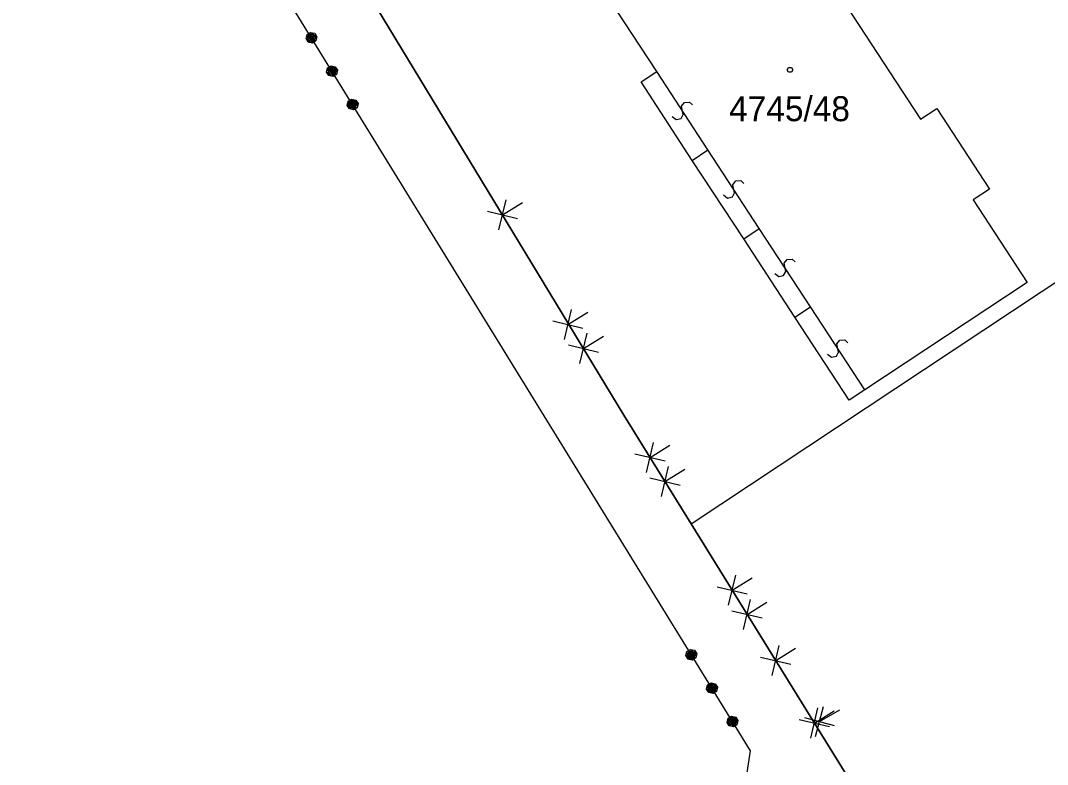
# Model space of a CAD drawing. Extents: x -266179 to -264727, y -1243225 to -1241702.
# Drawn here: x -265771.7 to -265705.9, y -1242086.5 to -1242038.9 of the extents above; entities that cross this region are included whole.
import ezdxf

# ---------------------------------------------------------------- set-up
doc = ezdxf.new("R2010")
doc.units = 0
for name, color, linetype in [('Vrstva 1', 7, 'Continuous'), ('Vrstva 19', 7, 'Continuous'), ('Vrstva 2', 7, 'Continuous'), ('Vrstva 21', 7, 'Continuous')]:
    doc.layers.add(name, color=color, linetype=linetype)

msp = doc.modelspace()

# ---------------------------------------------------------------- linework, layer by layer
at = {"layer": 'Vrstva 1'}
for p, q in [((-265771.66, -1242000.45), (-265733.03, -1242064.16)), ((-265720.51, -1242035.32), (-265714.05, -1242045.2)), ((-265730.93, -1242042.16), (-265734.17, -1242037.2)), ((-265724.93, -1242085.65), (-265754.18, -1242038.14)), ((-265731.93, -1242042.82), (-265730.93, -1242042.16)), ((-265728.65, -1242047.85), (-265731.93, -1242042.82)), ((-265714.05, -1242045.2), (-265713, -1242044.52)), ((-265713, -1242044.52), (-265709.62, -1242049.7)), ((-265725.36, -1242052.87), (-265728.65, -1242047.85)), ((-265709.62, -1242049.7), (-265710.67, -1242050.38)), ((-265710.67, -1242050.38), (-265707.22, -1242055.66)), ((-265722.08, -1242057.89), (-265725.36, -1242052.87)), ((-265728.73, -1242071.12), (-265701.71, -1242053.21)), ((-265707.22, -1242055.66), (-265717.61, -1242062.55)), ((-265718.61, -1242063.21), (-265722.08, -1242057.89)), ((-265717.61, -1242062.55), (-265718.61, -1242063.21)), ((-265733.03, -1242064.16), (-265728.73, -1242071.12)), ((-265728.73, -1242071.12), (-265715.42, -1242092.63)), ((-265733.05, -1242138.92), (-265724.93, -1242085.65))]:
    msp.add_line(p, q, dxfattribs=at)
msp.add_lwpolyline([(-265722.31, -1242041.9), (-265722.22, -1242042.05), (-265722.31, -1242042.2), (-265722.49, -1242042.2), (-265722.58, -1242042.05), (-265722.49, -1242041.9)], close=True, dxfattribs=at)
at = {"layer": 'Vrstva 19'}
for p, q in [((-265724.93, -1242085.65), (-265754.18, -1242038.14)), ((-265733.05, -1242138.92), (-265724.93, -1242085.65))]:
    msp.add_line(p, q, dxfattribs=at)
for points in [[(-265753.378, -1242040.054), (-265753.316, -1242039.793), (-265753.087, -1242039.651), (-265752.825, -1242039.713), (-265752.683, -1242039.943), (-265752.746, -1242040.204), (-265752.975, -1242040.346), (-265753.237, -1242040.284), (-265753.378, -1242040.054), (-265753.323, -1242040.067), (-265753.198, -1242040.271), (-265753.098, -1242040.281), (-265753.297, -1242039.957), (-265753.271, -1242039.847), (-265752.998, -1242040.29), (-265752.93, -1242040.248), (-265753.203, -1242039.805), (-265753.135, -1242039.763), (-265752.862, -1242040.206), (-265752.789, -1242040.172), (-265753.062, -1242039.73), (-265752.972, -1242039.722), (-265752.757, -1242040.071), (-265752.716, -1242039.986), (-265752.841, -1242039.782)], [(-265752.062, -1242042.191), (-265752, -1242041.93), (-265751.77, -1242041.788), (-265751.508, -1242041.85), (-265751.367, -1242042.08), (-265751.429, -1242042.341), (-265751.659, -1242042.483), (-265751.92, -1242042.421), (-265752.062, -1242042.191), (-265752.023, -1242042.179), (-265751.897, -1242042.383), (-265751.787, -1242042.409), (-265751.996, -1242042.068), (-265751.97, -1242041.958), (-265751.676, -1242042.435), (-265751.608, -1242042.393), (-265751.902, -1242041.916), (-265751.834, -1242041.874), (-265751.54, -1242042.351), (-265751.472, -1242042.309), (-265751.766, -1242041.832), (-265751.656, -1242041.859), (-265751.446, -1242042.199), (-265751.42, -1242042.089), (-265751.546, -1242041.885)], [(-265750.745, -1242044.328), (-265750.683, -1242044.066), (-265750.453, -1242043.925), (-265750.192, -1242043.987), (-265750.05, -1242044.217), (-265750.112, -1242044.478), (-265750.342, -1242044.62), (-265750.604, -1242044.558), (-265750.745, -1242044.328), (-265750.716, -1242044.298), (-265750.59, -1242044.503), (-265750.48, -1242044.529), (-265750.69, -1242044.188), (-265750.654, -1242044.095), (-265750.37, -1242044.555), (-265750.302, -1242044.513), (-265750.58, -1242044.062), (-265750.517, -1242044.011), (-265750.239, -1242044.463), (-265750.171, -1242044.421), (-265750.449, -1242043.969), (-265750.355, -1242043.97), (-265750.129, -1242044.336), (-265750.098, -1242044.235), (-265750.245, -1242043.996)], [(-265729.057, -1242079.559), (-265728.994, -1242079.298), (-265728.765, -1242079.156), (-265728.503, -1242079.218), (-265728.362, -1242079.448), (-265728.424, -1242079.71), (-265728.654, -1242079.851), (-265728.915, -1242079.789), (-265729.057, -1242079.559), (-265729.002, -1242079.572), (-265728.876, -1242079.777), (-265728.776, -1242079.786), (-265728.975, -1242079.462), (-265728.949, -1242079.352), (-265728.676, -1242079.795), (-265728.608, -1242079.753), (-265728.881, -1242079.31), (-265728.813, -1242079.268), (-265728.54, -1242079.711), (-265728.467, -1242079.678), (-265728.74, -1242079.235), (-265728.651, -1242079.227), (-265728.436, -1242079.576), (-265728.394, -1242079.492), (-265728.52, -1242079.287)], [(-265727.74, -1242081.696), (-265727.678, -1242081.435), (-265727.448, -1242081.293), (-265727.187, -1242081.355), (-265727.045, -1242081.585), (-265727.107, -1242081.847), (-265727.337, -1242081.988), (-265727.598, -1242081.926), (-265727.74, -1242081.696), (-265727.701, -1242081.684), (-265727.575, -1242081.888), (-265727.465, -1242081.914), (-265727.674, -1242081.574), (-265727.648, -1242081.464), (-265727.355, -1242081.941), (-265727.286, -1242081.899), (-265727.58, -1242081.422), (-265727.512, -1242081.38), (-265727.218, -1242081.857), (-265727.15, -1242081.815), (-265727.444, -1242081.338), (-265727.334, -1242081.364), (-265727.124, -1242081.705), (-265727.098, -1242081.594), (-265727.224, -1242081.39)], [(-265726.423, -1242083.833), (-265726.361, -1242083.572), (-265726.131, -1242083.43), (-265725.87, -1242083.492), (-265725.728, -1242083.722), (-265725.79, -1242083.984), (-265726.02, -1242084.125), (-265726.282, -1242084.063), (-265726.423, -1242083.833), (-265726.394, -1242083.804), (-265726.269, -1242084.008), (-265726.158, -1242084.034), (-265726.368, -1242083.694), (-265726.332, -1242083.601), (-265726.048, -1242084.06), (-265725.98, -1242084.018), (-265726.258, -1242083.567), (-265726.195, -1242083.517), (-265725.917, -1242083.968), (-265725.849, -1242083.926), (-265726.127, -1242083.475), (-265726.033, -1242083.475), (-265725.807, -1242083.841), (-265725.776, -1242083.74), (-265725.923, -1242083.502)]]:
    msp.add_lwpolyline(points, dxfattribs=at)
at = {"layer": 'Vrstva 2'}
for p, q in [((-265727.65, -1242047.18), (-265730.93, -1242042.16)), ((-265728.65, -1242047.85), (-265727.65, -1242047.18)), ((-265724.36, -1242052.21), (-265727.65, -1242047.18)), ((-265725.36, -1242052.87), (-265724.36, -1242052.21)), ((-265721.08, -1242057.23), (-265724.36, -1242052.21)), ((-265722.08, -1242057.89), (-265721.08, -1242057.23)), ((-265717.61, -1242062.55), (-265721.08, -1242057.23))]:
    msp.add_line(p, q, dxfattribs=at)
for points in [[(-265729.945, -1242045.039), (-265729.683, -1242045.238), (-265729.372, -1242045.166), (-265729.239, -1242044.912), (-265729.346, -1242044.384), (-265729.149, -1242044.136), (-265728.836, -1242044.122), (-265728.635, -1242044.301)], [(-265726.66, -1242050.064), (-265726.398, -1242050.263), (-265726.087, -1242050.191), (-265725.954, -1242049.937), (-265726.061, -1242049.409), (-265725.864, -1242049.161), (-265725.551, -1242049.147), (-265725.35, -1242049.326)], [(-265723.375, -1242055.089), (-265723.113, -1242055.288), (-265722.802, -1242055.216), (-265722.669, -1242054.962), (-265722.776, -1242054.434), (-265722.579, -1242054.186), (-265722.266, -1242054.172), (-265722.065, -1242054.351)], [(-265720, -1242060.258), (-265719.739, -1242060.458), (-265719.428, -1242060.386), (-265719.295, -1242060.132), (-265719.4, -1242059.604), (-265719.204, -1242059.356), (-265718.89, -1242059.343), (-265718.69, -1242059.522)]]:
    msp.add_lwpolyline(points, dxfattribs=at)
at = {"layer": 'Vrstva 21'}
for p, q in [((-265771.66, -1242000.45), (-265733.03, -1242064.16)), ((-265733.03, -1242064.16), (-265771.66, -1242000.45)), ((-265724.93, -1242085.65), (-265754.18, -1242038.14)), ((-265741.043, -1242052.296), (-265740.572, -1242050.372)), ((-265740.808, -1242051.334), (-265739.525, -1242050.556)), ((-265741.769, -1242051.098), (-265739.846, -1242051.569)), ((-265736.841, -1242059.322), (-265736.385, -1242057.395)), ((-265737.576, -1242058.131), (-265735.65, -1242058.586)), ((-265736.613, -1242058.358), (-265735.337, -1242057.57)), ((-265735.857, -1242060.846), (-265735.386, -1242058.923)), ((-265735.622, -1242059.884), (-265734.339, -1242059.106)), ((-265736.583, -1242059.649), (-265734.66, -1242060.12)), ((-265733.03, -1242064.16), (-265728.73, -1242071.12)), ((-265728.73, -1242071.12), (-265733.03, -1242064.16)), ((-265731.587, -1242067.83), (-265731.131, -1242065.904)), ((-265731.359, -1242066.867), (-265730.083, -1242066.079)), ((-265732.322, -1242066.639), (-265730.396, -1242067.095)), ((-265730.629, -1242069.376), (-265730.173, -1242067.45)), ((-265730.401, -1242068.413), (-265729.125, -1242067.625)), ((-265731.364, -1242068.185), (-265729.438, -1242068.641)), ((-265728.73, -1242071.12), (-265715.42, -1242092.63)), ((-265715.42, -1242092.63), (-265728.73, -1242071.12)), ((-265726.326, -1242076.336), (-265725.873, -1242074.408)), ((-265726.099, -1242075.372), (-265724.824, -1242074.583)), ((-265727.063, -1242075.145), (-265725.136, -1242075.599)), ((-265725.375, -1242077.885), (-265724.919, -1242075.958)), ((-265725.147, -1242076.922), (-265723.871, -1242076.133)), ((-265726.11, -1242076.694), (-265724.184, -1242077.149)), ((-265723.54, -1242080.838), (-265723.086, -1242078.911)), ((-265723.313, -1242079.875), (-265722.038, -1242079.085)), ((-265724.277, -1242079.648), (-265722.35, -1242080.102)), ((-265721.064, -1242084.839), (-265720.61, -1242082.912)), ((-265720.837, -1242083.875), (-265719.561, -1242083.086)), ((-265720.772, -1242084.737), (-265720.257, -1242082.825)), ((-265720.515, -1242083.781), (-265719.214, -1242083.033)), ((-265721.8, -1242083.648), (-265719.873, -1242084.102)), ((-265721.47, -1242083.523), (-265719.559, -1242084.038)), ((-265733.05, -1242138.92), (-265724.93, -1242085.65))]:
    msp.add_line(p, q, dxfattribs=at)

# ---------------------------------------------------------------- texts
at = {"layer": 'Vrstva 1'}
msp.add_text('4745/48', height=1.6, dxfattribs=at).set_placement((-265726.291, -1242045.34))

doc.saveas('drawing.dxf')
